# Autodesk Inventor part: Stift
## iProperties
Shininess: 64.0
Length Units: 11269
Angle Units: 11279
Time Units: 11290
Mass Units: 11283
Length Display Precision: 3
Angle Display Precision: 2
Compacted: True
Part Number: Stift
Document SubType Name: Modeling
Created: 2006-04
Material: Standard
Designer: IQ-Man
Manufacturer: Standard
Standards Organization: Custom
Density: 0.0
Volumn: 0.0
Area: 0.0
PropertySet Name: Model Information
Control State: 0
Master: False
Checked Out: False
Author: IQ-Man
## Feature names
1. Extrusion1
